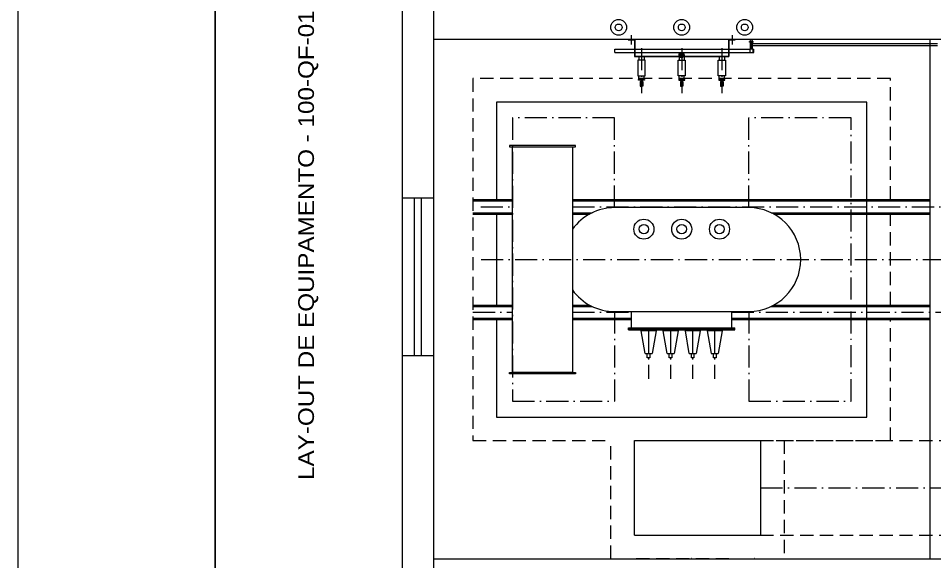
# Model space of a CAD drawing. Extents: x -4160 to -2690, y -474 to 714.
# Drawn here: x -3529.8 to -3413.5, y 222.4 to 291.3 of the extents above; entities that cross this region are included whole.
import ezdxf
from ezdxf.enums import TextEntityAlignment as Align

# ---------------------------------------------------------------- set-up
doc = ezdxf.new("R2010")
doc.units = 0
doc.header["$LTSCALE"] = 0.56
doc.linetypes.add('DOT_DASHED', pattern=[7.7, 5, -1.2, 0.3, -1.2])
doc.linetypes.add('MEDIUM_DASHED', pattern=[4.5, 3, -1.5])
for name, color, linetype, lineweight in [('1', 7, 'Continuous', 25), ('2', 7, 'Continuous', 25), ('4', 7, 'Continuous', 25), ('5', 7, 'Continuous', 35)]:
    doc.layers.add(name, color=color, linetype=linetype, lineweight=lineweight)

msp = doc.modelspace()

# ---------------------------------------------------------------- hatches: boundary and pattern name
at = {"layer": '2'}
msp.add_hatch(color=256, dxfattribs=at).paths.add_polyline_path([(-3445.5433, 286.2999, 1), (-3445.5433, 286.9484, 1)])

# ---------------------------------------------------------------- linework, layer by layer
at = {"layer": '1'}
for p, q in [((-3481.0303, 301.6824), (-3481.0303, 268.4824)), ((-3477.0303, 288.6544), (-3407.0303, 288.6544)), ((-3452.3303, 288.6464), (-3452.3303, 288.5864)), ((-3452.3303, 288.6464), (-3451.4703, 288.6464)), ((-3452.3303, 288.5864), (-3451.5303, 288.5864)), ((-3451.5303, 288.5864), (-3451.5303, 286.4464)), ((-3439.5903, 288.6464), (-3439.5903, 286.5064)), ((-3439.5303, 288.5864), (-3439.5303, 286.4464)), ((-3439.5303, 288.5864), (-3438.7303, 288.5864)), ((-3436.8103, 288.3464), (-3436.8983, 288.3464)), ((-3436.8983, 288.2664), (-3436.8983, 288.3464)), ((-3436.8103, 288.2664), (-3436.8983, 288.2664)), ((-3436.8103, 287.4104), (-3436.8103, 288.4784)), ((-3436.8103, 288.4784), (-3436.7703, 288.4784)), ((-3436.7703, 287.4104), (-3436.7703, 288.4784)), ((-3436.7463, 288.4504), (-3436.7463, 287.7744)), ((-3436.7463, 288.4504), (-3436.6023, 288.4504)), ((-3436.6023, 288.4504), (-3436.6023, 287.7744)), ((-3436.5783, 287.4104), (-3436.5783, 288.4784)), ((-3436.5783, 288.4784), (-3436.5423, 288.4784)), ((-3436.5423, 287.4104), (-3436.5423, 288.4784)), ((-3436.5423, 288.3464), (-3436.4543, 288.3464)), ((-3436.5423, 288.2664), (-3436.4543, 288.2664)), ((-3436.4543, 288.2664), (-3436.4543, 288.3464)), ((-3414.0303, 288.6544), (-3414.0303, 222.6544)), ((-3454.0143, 287.3624), (-3436.8503, 287.3624)), ((-3454.0143, 286.9624), (-3454.0143, 287.3624)), ((-3436.7463, 287.7744), (-3436.6023, 287.7744)), ((-3436.5423, 288.0984), (-3413.0303, 288.0984)), ((-3436.5423, 287.8584), (-3413.0303, 287.8584)), ((-3436.4983, 287.3624), (-3436.3823, 287.3624)), ((-3436.3823, 286.9624), (-3436.3823, 287.3624)), ((-3454.0143, 286.9624), (-3436.8503, 286.9624)), ((-3451.5303, 286.4464), (-3439.5303, 286.4464)), ((-3450.9583, 286.4464), (-3450.9583, 285.9824)), ((-3450.3023, 286.4464), (-3450.3023, 285.9824)), ((-3445.8583, 286.4464), (-3445.8583, 285.9824)), ((-3445.2023, 286.4464), (-3445.2023, 285.9824)), ((-3440.7583, 286.4464), (-3440.7583, 285.9824)), ((-3440.1023, 286.4464), (-3440.1023, 285.9824)), ((-3436.4983, 286.9624), (-3436.3823, 286.9624)), ((-3450.9583, 283.5224), (-3450.9583, 283.9904)), ((-3450.3023, 283.5224), (-3450.3023, 283.9904)), ((-3445.8583, 283.5224), (-3445.8583, 283.9904)), ((-3445.2023, 283.5224), (-3445.2023, 283.9904)), ((-3440.7583, 283.5224), (-3440.7583, 283.9904)), ((-3440.1023, 283.5224), (-3440.1023, 283.9904)), ((-3450.7903, 283.2944), (-3450.7903, 282.7024)), ((-3450.7903, 283.2944), (-3450.7103, 283.2944)), ((-3450.7903, 282.7024), (-3450.7103, 282.7024)), ((-3450.7103, 283.4464), (-3450.7103, 282.6504)), ((-3450.7103, 282.6504), (-3450.5503, 282.6504)), ((-3450.5503, 283.4464), (-3450.5503, 282.6504)), ((-3450.4703, 283.2944), (-3450.5503, 283.2944)), ((-3450.4703, 282.7024), (-3450.5503, 282.7024)), ((-3450.4703, 283.2944), (-3450.4703, 282.7024)), ((-3445.6903, 283.2944), (-3445.6903, 282.7024)), ((-3445.6903, 283.2944), (-3445.6103, 283.2944)), ((-3445.6903, 282.7024), (-3445.6103, 282.7024)), ((-3445.6103, 283.4464), (-3445.6103, 282.6504)), ((-3445.4503, 282.6504), (-3445.6103, 282.6504)), ((-3445.4503, 283.4464), (-3445.4503, 282.6504)), ((-3445.3703, 283.2944), (-3445.4503, 283.2944)), ((-3445.3703, 282.7024), (-3445.4503, 282.7024)), ((-3445.3703, 283.2944), (-3445.3703, 282.7024)), ((-3440.5903, 283.2944), (-3440.5903, 282.7024)), ((-3440.5903, 283.2944), (-3440.5103, 283.2944)), ((-3440.5903, 282.7024), (-3440.5103, 282.7024)), ((-3440.5103, 283.4464), (-3440.5103, 282.6504)), ((-3440.3503, 282.6504), (-3440.5103, 282.6504)), ((-3440.3503, 283.4464), (-3440.3503, 282.6504)), ((-3440.2703, 283.2944), (-3440.3503, 283.2944)), ((-3440.2703, 282.7024), (-3440.3503, 282.7024)), ((-3440.2703, 283.2944), (-3440.2703, 282.7024)), ((-3422.0303, 280.6544), (-3469.0303, 280.6544)), ((-3469.0303, 280.6544), (-3469.0303, 268.2784)), ((-3481.0303, 268.4824), (-3477.0303, 268.4824)), ((-3481.0303, 268.4824), (-3481.0303, 248.4824)), ((-3479.4823, 268.4824), (-3479.4823, 248.4824)), ((-3478.5903, 268.4824), (-3478.5903, 248.4824)), ((-3477.0303, 268.4824), (-3477.0303, 251.2784)), ((-3469.0303, 266.4264), (-3469.0303, 254.8784)), ((-3469.0303, 253.0264), (-3469.0303, 240.6544)), ((-3477.0303, 250.1904), (-3477.0303, 248.4824)), ((-3481.0303, 248.4824), (-3477.0303, 248.4824)), ((-3481.0303, 248.4824), (-3481.0303, 198.2664)), ((-3477.0303, 248.4824), (-3477.0303, 198.2664)), ((-3477.0303, 222.6544), (-3407.0303, 222.6544))]:
    msp.add_line(p, q, dxfattribs=at)
at = {"layer": '1', "linetype": 'DOT_DASHED'}
for p, q in [((-3451.9303, 289.1544), (-3451.9303, 287.9824)), ((-3439.1303, 289.1544), (-3439.1303, 287.9824)), ((-3450.6303, 287.5024), (-3450.6303, 281.7824)), ((-3445.5303, 287.5024), (-3445.5303, 281.7824)), ((-3440.4303, 287.5024), (-3440.4303, 281.7824))]:
    msp.add_line(p, q, dxfattribs=at)
at = {"layer": '1', "linetype": 'MEDIUM_DASHED'}
for p, q in [((-3472.0303, 283.6544), (-3472.0303, 237.6544)), ((-3419.0303, 283.6544), (-3472.0303, 283.6544)), ((-3419.0303, 268.2784), (-3419.0303, 283.6544)), ((-3419.0303, 254.8784), (-3419.0303, 266.4264)), ((-3419.0303, 237.6544), (-3419.0303, 253.0144)), ((-3472.0303, 237.6544), (-3454.5303, 237.6544)), ((-3433.5303, 237.6544), (-3419.0303, 237.6544))]:
    msp.add_line(p, q, dxfattribs=at)
at = {"layer": '1'}
for points in [[(-3477.0303, 301.6824), (-3477.0303, 268.4824), (-3477.0303, 248.4824)], [(-3451.4703, 288.6464), (-3451.4703, 286.5064), (-3439.5903, 286.5064)], [(-3439.5903, 288.6464), (-3438.7303, 288.6464), (-3438.7303, 288.5864)], [(-3469.0303, 240.6544), (-3422.0303, 240.6544), (-3422.0303, 280.6544)]]:
    msp.add_lwpolyline(points, dxfattribs=at)
for points in [[(-3436.8503, 286.9064), (-3436.8503, 287.4104), (-3436.4983, 287.4104), (-3436.4983, 286.9064)], [(-3451.0823, 283.9904), (-3450.1823, 283.9904), (-3450.1823, 285.9824), (-3451.0823, 285.9824)], [(-3445.0823, 283.9904), (-3445.9783, 283.9904), (-3445.9783, 285.9824), (-3445.0823, 285.9824)], [(-3439.9823, 283.9904), (-3440.8783, 283.9904), (-3440.8783, 285.9824), (-3439.9823, 285.9824)], [(-3450.2503, 283.4464), (-3451.0103, 283.4464), (-3451.0103, 283.5264), (-3450.2503, 283.5264)], [(-3445.9103, 283.4464), (-3445.1503, 283.4464), (-3445.1503, 283.5264), (-3445.9103, 283.5264)], [(-3440.8103, 283.4464), (-3440.0503, 283.4464), (-3440.0503, 283.5264), (-3440.8103, 283.5264)]]:
    msp.add_lwpolyline(points, close=True, dxfattribs=at)
at = {"layer": '2'}
for p, q in [((-3444.2583, 288.6184), (-3444.2943, 288.6264)), ((-3437.0183, 267.2544), (-3454.0423, 267.2544)), ((-3454.0423, 254.0544), (-3437.0183, 254.0544)), ((-3451.8983, 251.9984), (-3451.8983, 254.0544)), ((-3439.1663, 251.9984), (-3439.1663, 254.0544)), ((-3452.3023, 251.9984), (-3438.7623, 251.9984)), ((-3452.3023, 251.7264), (-3452.3023, 251.9984)), ((-3452.3023, 251.8624), (-3438.7623, 251.8624)), ((-3452.3023, 251.7264), (-3438.7623, 251.7264)), ((-3448.7863, 251.6024), (-3449.2863, 248.7184)), ((-3445.9863, 251.6024), (-3447.9063, 251.6024)), ((-3447.9063, 251.6024), (-3447.4063, 248.7184)), ((-3445.9863, 251.6024), (-3446.4863, 248.7184)), ((-3443.1863, 251.6024), (-3443.6863, 248.7184)), ((-3440.3863, 251.6024), (-3440.8863, 248.7184)), ((-3438.7623, 251.7264), (-3438.7623, 251.9984)), ((-3450.1743, 248.7184), (-3449.2863, 248.7184)), ((-3447.3743, 248.7184), (-3446.4863, 248.7184)), ((-3444.5743, 248.7184), (-3443.6863, 248.7184)), ((-3441.7743, 248.7184), (-3440.8863, 248.7184)), ((-3444.2583, 222.6904), (-3444.2943, 222.6784)), ((-3436.2583, 222.6904), (-3436.2943, 222.6784))]:
    msp.add_line(p, q, dxfattribs=at)
at = {"layer": '2', "linetype": 'DOT_DASHED'}
for p, q in [((-3467.0303, 278.6544), (-3467.0303, 242.6544)), ((-3454.0423, 278.6544), (-3467.0303, 278.6544)), ((-3454.0423, 267.2544), (-3454.0423, 278.6544)), ((-3437.0183, 267.2544), (-3437.0183, 278.6544)), ((-3424.0303, 278.6544), (-3437.0183, 278.6544)), ((-3424.0303, 242.6544), (-3424.0303, 278.6544)), ((-3454.0423, 254.0544), (-3454.0423, 242.6544)), ((-3437.0183, 254.0544), (-3437.0183, 242.6544)), ((-3449.7463, 251.6024), (-3449.7463, 245.5224)), ((-3446.9463, 251.6024), (-3446.9463, 245.5224)), ((-3444.1463, 251.6024), (-3444.1463, 245.5224)), ((-3441.3463, 251.6024), (-3441.3463, 245.5224)), ((-3467.0303, 242.6544), (-3454.0423, 242.6544)), ((-3437.0183, 242.6544), (-3424.0303, 242.6544))]:
    msp.add_line(p, q, dxfattribs=at)
at = {"layer": '2'}
for points in [[(-3467.4103, 274.9904), (-3459.0263, 274.9904), (-3459.0263, 275.1544), (-3467.4103, 275.1544)], [(-3467.0303, 246.3184), (-3467.0303, 274.9784), (-3459.4063, 274.9784), (-3459.4063, 246.3184)], [(-3449.5623, 248.7184), (-3449.5623, 248.1544), (-3449.8983, 248.1544), (-3449.8983, 248.7184)], [(-3446.7623, 248.7184), (-3446.7623, 248.1544), (-3447.0983, 248.1544), (-3447.0983, 248.7184)], [(-3443.9663, 248.7184), (-3443.9663, 248.1544), (-3444.2983, 248.1544), (-3444.2983, 248.7184)], [(-3441.1663, 248.7184), (-3441.1663, 248.1544), (-3441.4983, 248.1544), (-3441.4983, 248.7184)], [(-3467.4103, 246.3184), (-3459.0263, 246.3184), (-3459.0263, 246.1504), (-3467.4103, 246.1504)]]:
    msp.add_lwpolyline(points, close=True, dxfattribs=at)
for points in [[(-3448.7863, 251.6024), (-3450.7063, 251.6024), (-3450.2063, 248.7184)], [(-3443.1863, 251.6024), (-3445.1063, 251.6024), (-3444.6063, 248.7184)], [(-3440.3863, 251.6024), (-3442.3063, 251.6024), (-3441.8063, 248.7184)]]:
    msp.add_lwpolyline(points, dxfattribs=at)
for centre, radius in [((-3453.5313, 290.1534), 1), ((-3445.5313, 290.1534), 1), ((-3437.5313, 290.1534), 1), ((-3453.5313, 290.1534), 0.424), ((-3445.5313, 290.1534), 0.424), ((-3437.5313, 290.1534), 0.424), ((-3445.5433, 286.6241), 0.3243), ((-3450.3313, 264.5208), 1.27), ((-3450.3313, 264.5208), 0.5988), ((-3445.5313, 264.5208), 1.27), ((-3445.5313, 264.5208), 0.5988), ((-3440.7313, 264.5208), 1.27), ((-3440.7313, 264.5208), 0.5988)]:
    msp.add_circle(centre, radius, dxfattribs=at)
for centre, start, end in [((-3454.0433, 260.6534), 90, 144.33511), ((-3437.0193, 260.6534), 270, 90), ((-3454.0433, 260.6534), 215.66489, 270)]:
    msp.add_arc(centre, 6.6, start, end, dxfattribs=at)
at = {"layer": '4'}
for p, q in [((-3472.0303, 268.2784), (-3467.0303, 268.2784)), ((-3472.0303, 268.1024), (-3467.0303, 268.1024)), ((-3459.4063, 268.2784), (-3414.0303, 268.2784)), ((-3459.4063, 268.1024), (-3414.0303, 268.1024)), ((-3472.0303, 266.6024), (-3467.0303, 266.6024)), ((-3472.0303, 266.4264), (-3467.0303, 266.4264)), ((-3459.4063, 266.6024), (-3456.8983, 266.6024)), ((-3459.4063, 266.4264), (-3457.2423, 266.4264)), ((-3434.1623, 266.6024), (-3414.0303, 266.6024)), ((-3433.8223, 266.4264), (-3414.0303, 266.4264)), ((-3472.0303, 254.8784), (-3467.0303, 254.8784)), ((-3472.0303, 254.7024), (-3467.0303, 254.7024)), ((-3459.4063, 254.8784), (-3457.2423, 254.8784)), ((-3459.4063, 254.7024), (-3456.8983, 254.7024)), ((-3434.1623, 254.7024), (-3414.0303, 254.7024)), ((-3433.8223, 254.8784), (-3414.0303, 254.8784)), ((-3472.0303, 253.2024), (-3467.0303, 253.2024)), ((-3472.0303, 253.0264), (-3467.0303, 253.0264)), ((-3459.4063, 253.2024), (-3451.8983, 253.2024)), ((-3459.4063, 253.0264), (-3451.8983, 253.0264)), ((-3439.1663, 253.2024), (-3414.0303, 253.2024)), ((-3439.1663, 253.0264), (-3414.0303, 253.0264)), ((-3451.5303, 225.6544), (-3435.5303, 225.6544))]:
    msp.add_line(p, q, dxfattribs=at)
at = {"layer": '4', "linetype": 'DOT_DASHED'}
for p, q in [((-3471.0303, 267.3544), (-3467.0303, 267.3544)), ((-3459.4063, 267.3544), (-3340.0743, 267.3544)), ((-3470.9863, 260.6544), (-3340.0743, 260.6544)), ((-3472.0303, 253.9544), (-3467.0303, 253.9544)), ((-3459.4063, 253.9544), (-3451.8983, 253.9544)), ((-3439.1663, 253.9544), (-3340.0743, 253.9544)), ((-3435.5303, 231.6544), (-3389.1023, 231.6544))]:
    msp.add_line(p, q, dxfattribs=at)
at = {"layer": '4', "linetype": 'MEDIUM_DASHED'}
for p, q in [((-3454.5303, 222.6544), (-3454.5303, 237.6544)), ((-3435.5303, 237.6544), (-3388.7023, 237.6544)), ((-3432.5303, 237.6544), (-3432.5303, 222.6544)), ((-3435.5303, 225.6544), (-3388.7023, 225.6544)), ((-3439.5303, 222.6544), (-3451.5303, 222.6544))]:
    msp.add_line(p, q, dxfattribs=at)
at = {"layer": '4'}
msp.add_lwpolyline([(-3451.5303, 225.6544), (-3451.5303, 237.6544), (-3435.5303, 237.6544), (-3435.5303, 225.6544)], dxfattribs=at)
at = {"layer": '5', "lineweight": 25}
msp.add_line((-3529.7642, 120.48), (-3529.7642, 417.4797), dxfattribs=at)
at = {"layer": '5'}
msp.add_lwpolyline([(-3504.7642, 130.48), (-3504.7642, 383.48), (-3330.7642, 383.48), (-3330.7642, 130.48)], close=True, dxfattribs=at)

# ---------------------------------------------------------------- texts
at = {"layer": '2', "width": 1.15}
msp.add_text('LAY-OUT DE EQUIPAMENTO - 100-QF-01', height=2, rotation=90, dxfattribs=at).set_placement((-3492.2231, 262.4866), align=Align.CENTER)

doc.saveas('drawing.dxf')
